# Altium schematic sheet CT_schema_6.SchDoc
size 278 x 170 mm
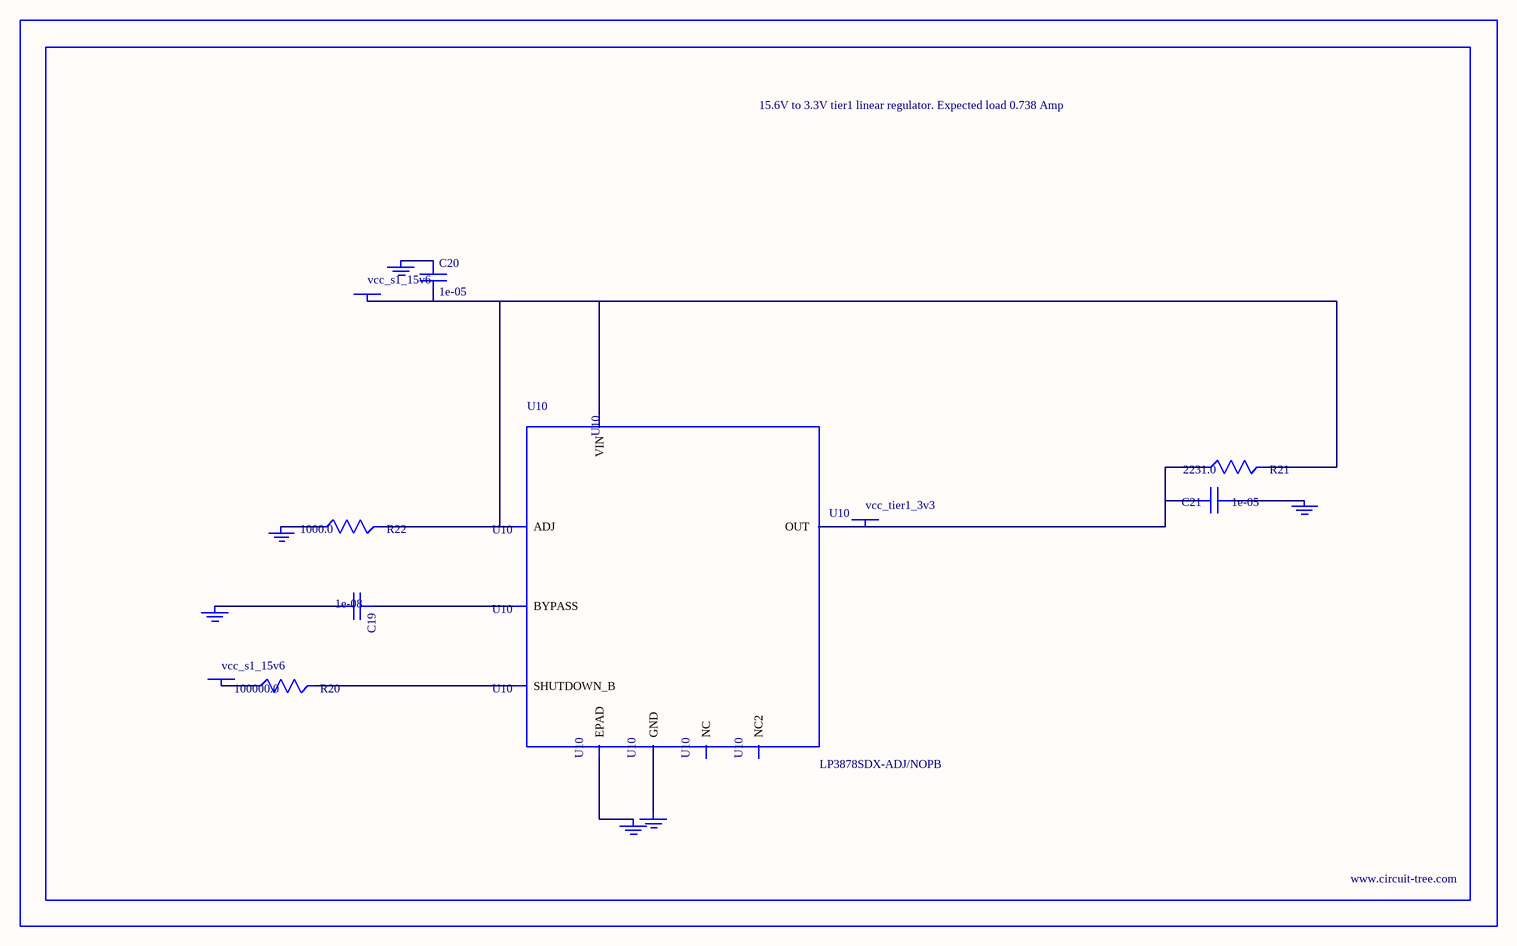
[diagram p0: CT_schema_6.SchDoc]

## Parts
BORDER5  (no value)
C19  1e-08  [C0402]
C20  1e-05  [C1210]
C21  1e-05  [C1210]
GND_INSTANCE_5_0  (no value)
GND_INSTANCE_5_1  (no value)
GND_INSTANCE_5_2  (no value)
GND_INSTANCE_5_3  (no value)
GND_INSTANCE_5_4  (no value)
GND_INSTANCE_5_5  (no value)
POWER_INSTANCE_5_0  vcc_s1_15v6
POWER_INSTANCE_5_1  vcc_s1_15v6
POWER_INSTANCE_5_2  vcc_tier1_3v3
R20  100000.0  [R0603]
R21  2231.0  [R0603]
R22  1000.0  [R0603]
U10  LP3878SDX-ADJ/NOPB  [WSON-8]

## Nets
NetC19_1: C19.1 U10.1(BYPASS)
NetC19_2: C19.2 GND_INSTANCE_5_0.0(GND)
NetC20_1: C20.1 GND_INSTANCE_5_1.0(GND)
NetC20_2: C20.2 POWER_INSTANCE_5_0.0(PWR) R21.2 R22.2 U10.4(VIN) U10.6(ADJ)
NetC21_1: C21.1 GND_INSTANCE_5_2.0(GND)
NetC21_2: C21.2 POWER_INSTANCE_5_2.0(PWR) R21.1 U10.5(OUT)
NetGND_INSTANCE_5_3_0: GND_INSTANCE_5_3.0(GND) R22.1
NetGND_INSTANCE_5_4_0: GND_INSTANCE_5_4.0(GND) U10.PAD(EPAD)
NetGND_INSTANCE_5_5_0: GND_INSTANCE_5_5.0(GND) U10.3(GND)
NetPOWER_INSTANCE_5_1_0: POWER_INSTANCE_5_1.0(PWR) R20.1
NetR20_2: R20.2 U10.8(SHUTDOWN_B)

Not connected (* = marked no-connect by the designer): U10 2(NC) 7(NC2)

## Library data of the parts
BORDER5 = BORDER_PAGE5
C19 = C0402C103K3RAC
C20 = C1210C106K5PACTU
C21 = GRM32DR61E106MA12L
GND_INSTANCE_5_0-GND_INSTANCE_5_5 = GND
POWER_INSTANCE_5_0-POWER_INSTANCE_5_2 = PWR
R20 = RC0603JR-07100KL
R21 = R21
R22 = RC0603JR-071KL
